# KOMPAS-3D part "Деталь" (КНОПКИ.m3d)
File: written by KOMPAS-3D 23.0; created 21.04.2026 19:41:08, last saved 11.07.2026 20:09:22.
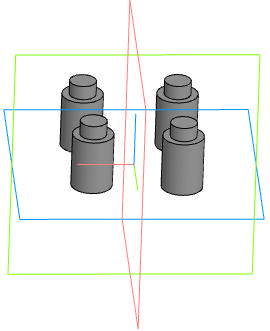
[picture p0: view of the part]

Document properties: Автор: D.LAB; Полное имя файла: C:\ЭЛЕКТРОНИКА\СХЕМЫ\Разное\ЦИФРОВОЙ ПРЕССОСТАТ ДЛЯ КОМПРЕССОРА\КОРПУС\1.0\КНОПКИ.m3d

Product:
- Part/product: Деталь
    Масса: 0.022746

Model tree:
1. Эскиз:1
2. Элемент выдавливания:2
     Расстояние 1 = 11.5
3. Эскиз:3  (with: Элемент выдавливания:2)
4. Элемент выдавливания:3
     Расстояние 1 = 3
